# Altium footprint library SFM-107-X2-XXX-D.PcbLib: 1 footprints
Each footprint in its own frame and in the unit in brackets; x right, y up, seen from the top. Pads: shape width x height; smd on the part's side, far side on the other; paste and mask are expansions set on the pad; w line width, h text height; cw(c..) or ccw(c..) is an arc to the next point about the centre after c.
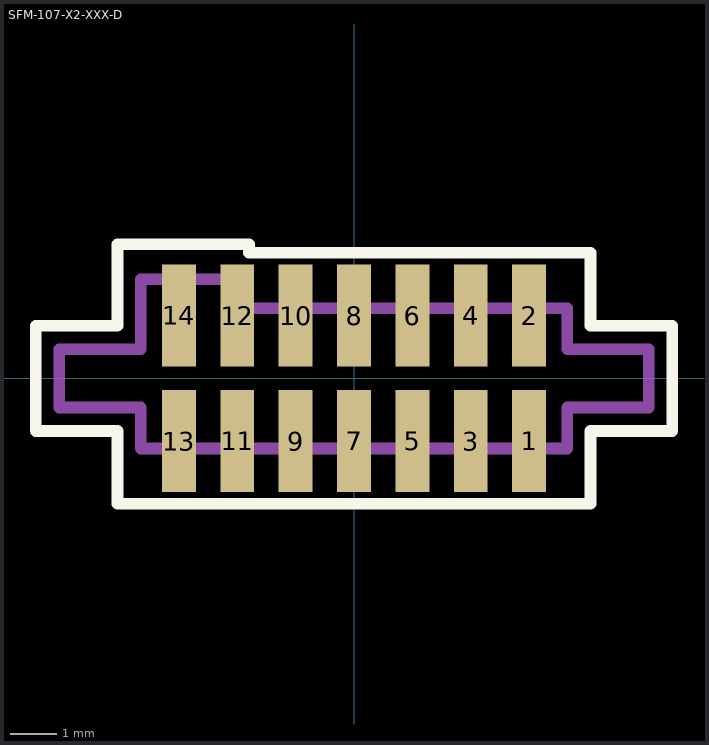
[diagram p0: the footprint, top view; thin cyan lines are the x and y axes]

## SFM-107-X2-XXX-D [mil]
pads (14):
  rect 29x87.5 smd mask+2: 1(150,-53.75) 2(150,53.75) 3(100,-53.75) 4(100,53.75) 5(50,-53.75) 6(50,53.75) 7(0,-53.75) 8(0,53.75) 9(-50,-53.75) 10(-50,53.75) 11(-100,-53.75) 12(-100,53.75) 13(-150,-53.75) 14(-150,53.75)
Top Overlay:
  lines w10: -272.5,-45 -272.5,45 -202.5,45 -202.5,115 -90,115 -90,107.5 202.5,107.5 202.5,45 272.5,45 272.5,-45 202.5,-45 202.5,-107.5 -202.5,-107.5 -202.5,-45 -272.5,-45
Mechanical 1:
  lines w10: -252.5,-25 -252.5,25 -182.5,25 -182.5,85 -102.5,85 -102.5,60 182.5,60 182.5,25 252.5,25 252.5,-25 182.5,-25 182.5,-60 -182.5,-60 -182.5,-25 -252.5,-25
  text "J1" at -17.57,-18 h30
